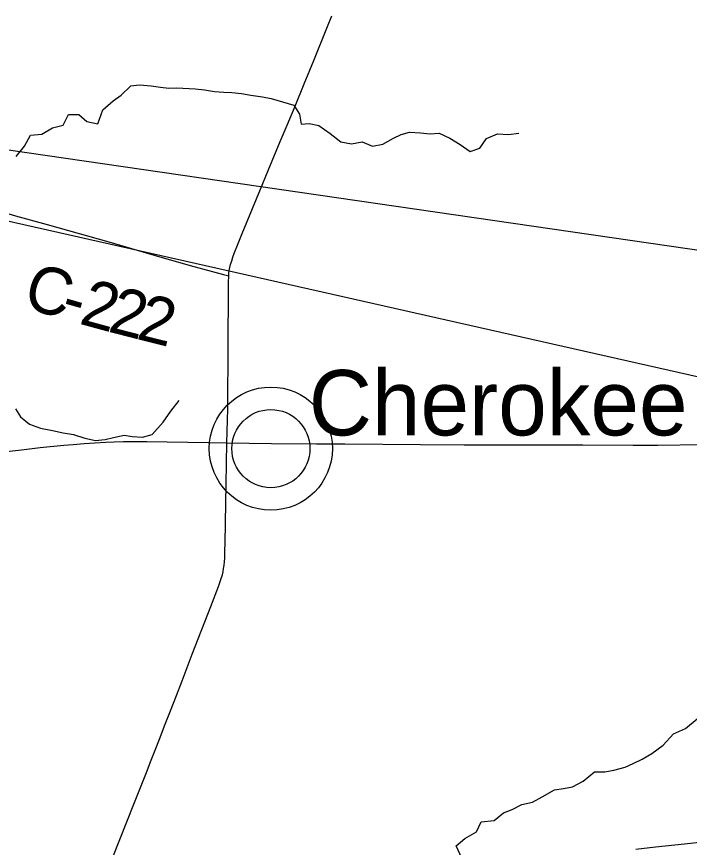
# Model space of a CAD drawing. Extents: x 0 to 34, y -5.4 to 22.
# Drawn here: x 6.58 to 7.394, y 16.492 to 17.496 of the extents above; entities that cross this region are included whole.
import ezdxf

# ---------------------------------------------------------------- set-up
doc = ezdxf.new("R2010")
doc.units = 0
for name, color, linetype in [('GM_X_County_Road', 7, 'Continuous'), ('GM_X_County_Road_Text', 7, 'Continuous'), ('GM_X_Minor_River', 7, 'Continuous'), ('GM_X_State_Route', 7, 'Continuous'), ('GM_X_Township_Road', 7, 'Continuous'), ('GM_X_Unincorporated', 7, 'Continuous'), ('GM_X_Unincorporated_Location', 7, 'Continuous'), ('GM_X_Unincorporated_Text', 7, 'Continuous'), ('SH_Data', 7, 'Continuous')]:
    doc.layers.add(name, color=color, linetype=linetype)

msp = doc.modelspace()

# ---------------------------------------------------------------- linework, layer by layer
at = {"layer": 'GM_X_County_Road'}
for points in [[(6.8345, 16.981), (6.8354, 17.022), (6.8359, 17.0994), (6.8363, 17.1653), (6.8364, 17.1704), (6.8365, 17.1753), (6.8367, 17.1827), (6.8367, 17.183), (6.837, 17.1862), (6.8374, 17.1894), (6.8382, 17.1931), (6.839, 17.1966), (6.8404, 17.2011), (6.8417, 17.2054), (6.8438, 17.2113), (6.8472, 17.2199), (6.8531, 17.2342), (6.875, 17.2877), (6.8844, 17.31), (6.8988, 17.3451), (6.9072, 17.3651), (6.9168, 17.3881), (6.9278, 17.4151), (6.9395, 17.4432), (6.956, 17.4841), (6.9615, 17.4973)], [(6.4661, 17.2918), (6.4875, 17.2844), (6.4984, 17.2805), (6.5451, 17.2655), (6.5788, 17.2556), (6.6171, 17.2448), (6.6916, 17.2239), (6.7465, 17.208), (6.7901, 17.1955), (6.8302, 17.1847), (6.8367, 17.183)], [(6.6965, 16.4804), (6.7049, 16.5017), (6.7219, 16.5444), (6.7371, 16.5829), (6.7429, 16.5975), (6.7476, 16.6097), (6.7528, 16.6231), (6.7598, 16.641), (6.7662, 16.6573), (6.7735, 16.6757), (6.7804, 16.6936), (6.7926, 16.7256), (6.8151, 16.7835), (6.8243, 16.8073), (6.8261, 16.8125), (6.8277, 16.8173), (6.829, 16.8215), (6.8298, 16.8252), (6.8305, 16.8293), (6.8312, 16.8332), (6.8316, 16.8374), (6.8319, 16.842), (6.8321, 16.8511), (6.8323, 16.8594), (6.8328, 16.8848), (6.8335, 16.9312), (6.8345, 16.981)]]:
    msp.add_lwpolyline(points, dxfattribs=at)
at = {"layer": 'GM_X_Minor_River'}
for points in [[(6.5798, 17.3272), (6.5898, 17.3395), (6.5972, 17.3527), (6.6109, 17.3543), (6.6235, 17.3617), (6.6364, 17.3649), (6.643, 17.3777), (6.6555, 17.3779), (6.6652, 17.3694), (6.6784, 17.3665), (6.6844, 17.3835), (6.697, 17.3943), (6.7066, 17.4013), (6.7185, 17.4125), (6.7288, 17.4138), (6.7431, 17.4125), (6.7541, 17.4111), (6.7643, 17.4098), (6.7741, 17.41), (6.796, 17.4089), (6.8074, 17.4076), (6.8195, 17.4058), (6.8308, 17.4049), (6.8406, 17.4044), (6.8523, 17.4034), (6.8633, 17.4013), (6.8776, 17.3992), (6.8878, 17.3971), (6.9017, 17.3931), (6.9153, 17.389), (6.9223, 17.3783), (6.9244, 17.3661), (6.9339, 17.3671), (6.9456, 17.3646), (6.9594, 17.3549), (6.9721, 17.3448), (6.9849, 17.3423), (6.9978, 17.3448), (7.0106, 17.3396), (7.0228, 17.3421), (7.0357, 17.3491), (7.0453, 17.3535), (7.0552, 17.3567), (7.0684, 17.3557), (7.0801, 17.3544), (7.0911, 17.3553), (7.1039, 17.3494), (7.1166, 17.3416), (7.1286, 17.3331), (7.1404, 17.337), (7.1481, 17.3487), (7.1618, 17.3545), (7.1747, 17.3539), (7.1872, 17.3552)], [(6.5789, 17.022), (6.5848, 17.0124), (6.5957, 17.0035), (6.6092, 16.9987), (6.6235, 16.9962), (6.6367, 16.993), (6.6492, 16.9912), (6.6627, 16.9868), (6.6756, 16.984), (6.6873, 16.9853), (6.6972, 16.9874), (6.7101, 16.9902), (6.7199, 16.9889), (6.7324, 16.9879), (6.7442, 16.9911), (6.7573, 17.0061), (6.7666, 17.0192), (6.7766, 17.0323)], [(7.3744, 16.6293), (7.3889, 16.6359), (7.4031, 16.6475)], [(7.1184, 16.4792), (7.1115, 16.4942), (7.1222, 16.5031), (7.1363, 16.5112), (7.1418, 16.5232), (7.1574, 16.5249), (7.1689, 16.5338), (7.1795, 16.5382), (7.191, 16.544), (7.2039, 16.5469), (7.2154, 16.5535), (7.2306, 16.5616), (7.2413, 16.5633), (7.2523, 16.5654), (7.2652, 16.5724), (7.2787, 16.5835), (7.2912, 16.5837), (7.3022, 16.5854), (7.3159, 16.589), (7.3258, 16.5934), (7.3364, 16.5989), (7.3483, 16.6055), (7.3617, 16.6159), (7.3744, 16.6293)]]:
    msp.add_lwpolyline(points, dxfattribs=at)
at = {"layer": 'GM_X_State_Route'}
msp.add_lwpolyline([(6.5491, 16.9685), (6.5862, 16.9727), (6.6086, 16.9753), (6.6372, 16.9783), (6.6487, 16.9792), (6.6619, 16.9803), (6.675, 16.9813), (6.6882, 16.982), (6.6982, 16.9824), (6.7096, 16.9827), (6.7224, 16.9829), (6.7375, 16.9827), (6.8118, 16.9814), (6.8345, 16.981), (6.8882, 16.9803), (6.9429, 16.9798), (6.9771, 16.9798), (7.0684, 16.9792), (7.1212, 16.9788), (7.2001, 16.9787), (7.2647, 16.9785), (7.3256, 16.9782), (7.3554, 16.9784), (7.4089, 16.9791)], dxfattribs=at)
at = {"layer": 'GM_X_Township_Road'}
msp.add_lwpolyline([(7.329, 16.49), (7.3525, 16.4927), (7.3877, 16.4964), (7.4242, 16.5004), (7.46, 16.504), (7.481, 16.5063), (7.515, 16.5097), (7.5428, 16.5127), (7.5459, 16.5131)], dxfattribs=at)
at = {"layer": 'GM_X_Unincorporated'}
for radius in [0.0744, 0.0472]:
    msp.add_circle((6.8876, 16.9741), radius, dxfattribs=at)
at = {"layer": 'GM_X_Unincorporated_Location'}
msp.add_line((6.8876, 16.9741), (6.8876, 16.9741), dxfattribs=at)
at = {"layer": 'SH_Data'}
msp.add_lwpolyline([(9.2327, 16.948), (5.505, 17.4894), (9.2327, 16.6485)], close=True, dxfattribs=at)

# ---------------------------------------------------------------- texts
at = {"layer": 'GM_X_County_Road_Text'}
for s, rotation, p in [('C', 343.3748, (6.586, 17.1456)), ('2', 344.6997, (6.6545, 17.1254)), ('2', 345.6002, (6.6892, 17.1159)), ('2', 346.0641, (6.7236, 17.107)), ('-', 343.902, (6.6313, 17.1321))]:
    msp.add_text(s, height=0.0568, rotation=rotation, dxfattribs=at).set_placement(p)
at = {"layer": 'GM_X_Unincorporated_Text'}
msp.add_text('Cherokee', height=0.07898, rotation=0, dxfattribs=at).set_placement((6.9335, 16.9901))

doc.saveas('drawing.dxf')
